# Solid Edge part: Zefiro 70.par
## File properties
Title: Zefiro 70
Author: DESYS
Template: Normal.par
Last saved by: i.fialdini
Revision: 38
Application: Solid Edge
Tipo di contenuto documento: 0
Precisione: 0.990
Document Number: 8206
Revision: 0
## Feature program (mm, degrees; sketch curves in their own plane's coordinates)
lofted protrusion "unnamed LoftedProtrusion 1"
sketch for "unnamed Cutout 1" plane through (0, 0, 0) normal (1, 0, 0) x-axis (0, 1, 0)
  arc centre (0, 843.7224) radius 911.7224 from (-345.5, 0) to (345.5, 0) ccw
extrude "unnamed Cutout 1" cut through
thinwall "unnamed Thinwall 1"
fillet "Rotondo_1" radius 3
sketch for "ExtrudedProtrusion_1" plane through (0, 0, -158) normal (0, 0, -1) x-axis (0, 1, 0)
extrude "ExtrudedProtrusion_1" add finite 10 along +normal
fillet "Rotondo_3" radius 50
sketch for "ScavoEstrusione_2" plane through (0, 0, -168) normal (0, 0, -1) x-axis (0, 1, 0)
extrude "ScavoEstrusione_2" cut finite 15 along -normal
sketch for "ExtrudedProtrusion_6" plane through (-0.0005, 0, -153) normal (0, 0, -1) x-axis (0, 1, 0)
extrude "ExtrudedProtrusion_6" add finite 30 along +normal
sketch for "Foro_1" plane through (0, 0, -183) normal (0, 0, -1) x-axis (0, 1, 0)
  hole centre (0, 0) bore radius 25
hole "Foro_1" diameter 50 through
fillet "Rotondo_5" radius 10
fillet "Rotondo_15" radius 10
fillet "Rotondo_22" radius 40
fillet "Rotondo_23" radius 5
sketch for "unnamed RevolvedProtrusion 1" plane through (0, 0, 0) normal (1, 0, 0) x-axis (0, 1, 0)
revolve "unnamed RevolvedProtrusion 1" add full turn 360 deg
fillet "Rotondo_24" radius 5
fillet "Rotondo_25" radius 7
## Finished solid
Body 1: solid body, 19 faces, 20 edges, 2 vertices.
  Faces by surface: blend 6, plane 5, cylinder 2, torus 2, cone 1, offset 1, spline 1, swept 1
  Edges by curve: intersection 12, circle 7, ellipse 1
Bounding box of the edges (mm; curved faces can reach further): 358.098 x 685.071 x 180.246, from (-178.8431, -342.5246, -183) to (179.2548, 342.546, -2.754).
Cylindrical faces by radius (mm): R25 x1, R911.7224 x1
Conical faces (half-angle, radius in mm at the cone's reference point): 38.6598 deg R35 x1
Toroidal faces (ring radius, tube radius in mm): R30 r5 x1, R35 r10 x1
Planar faces by outward normal: +z 1, -z 4
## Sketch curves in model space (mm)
arc centre (34.1412, 0, -35.003) radius 150 from (180, 0, 0) through (174.3705, 0, -88.2546) to (120, 0, -158)
arc centre (-34.1412, 0, -35.003) radius 150 from (-180, 0, 0) through (-174.3705, 0, -88.2546) to (-120, 0, -158)
arc centre (0, 69.0627, 116.5435) radius 300 from (0, 345.5, 0) through (0, 282.8795, -93.8902) to (0, 190, -158)
arc centre (0, -69.0627, 116.5435) radius 300 from (0, -345.5, 0) through (0, -282.8795, -93.8902) to (0, -190, -158)
ellipse centre (0, 0, -158) radii 190, 120
ellipse centre (0, 0, 0) radii 345.5, 180
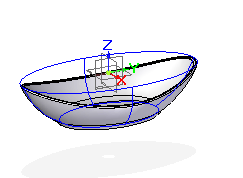
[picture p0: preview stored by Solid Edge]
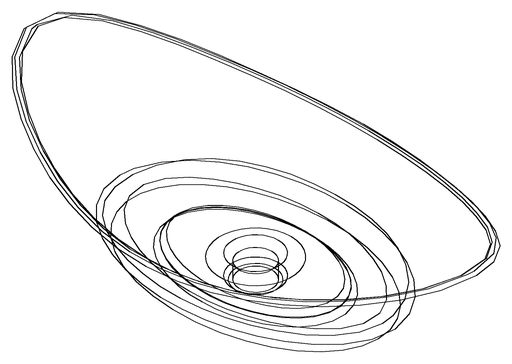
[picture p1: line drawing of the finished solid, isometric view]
